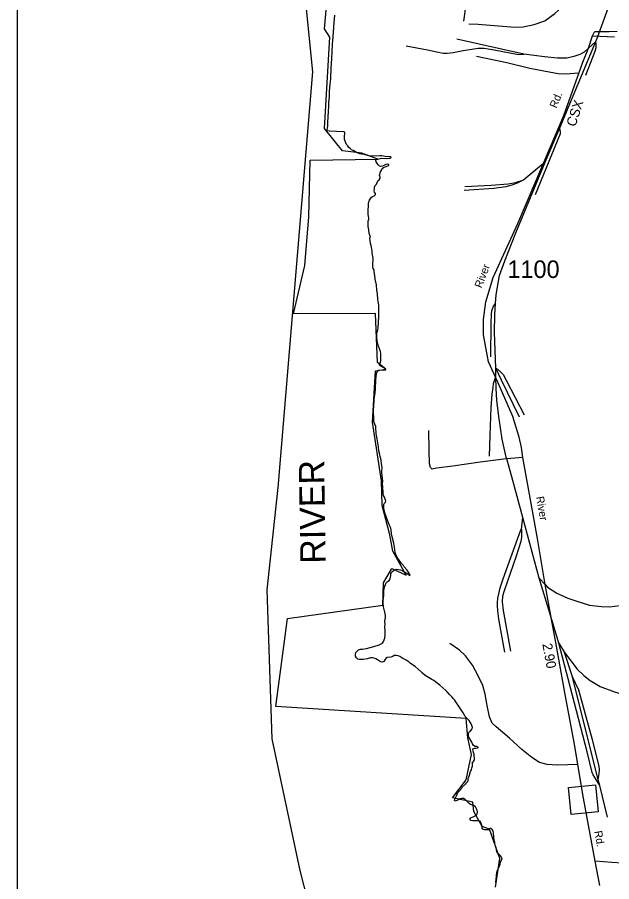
# Model space of a CAD drawing. Extents: x 1945482 to 2853149, y 66427 to 1015778.
# Drawn here: x 2313127 to 2318125, y 155248 to 162514 of the extents above; entities that cross this region are included whole.
import ezdxf

# ---------------------------------------------------------------- set-up
doc = ezdxf.new("R2010")
doc.units = 0
for name, color, linetype in [('Old_Level_11', 7, 'Continuous'), ('Old_Level_14', 7, 'Continuous'), ('Old_Level_17', 7, 'Continuous'), ('Old_Level_21', 7, 'Continuous'), ('Old_Level_28', 7, 'Continuous'), ('Old_Level_31', 7, 'Continuous'), ('Old_Level_32', 7, 'Continuous'), ('Old_Level_35', 7, 'Continuous'), ('Old_Level_44', 7, 'Continuous'), ('Old_Level_48', 7, 'Continuous'), ('Old_Level_49', 7, 'Continuous'), ('Old_Level_52', 7, 'Continuous'), ('Old_Level_60', 7, 'Continuous'), ('Old_Level_63', 7, 'Continuous'), ('Old_Level_8', 7, 'Continuous')]:
    doc.layers.add(name, color=color, linetype=linetype)

msp = doc.modelspace()

# ---------------------------------------------------------------- linework, layer by layer
at = {"layer": 'Old_Level_28'}
for points in [[(2318169.4, 162393.2), (2318104.3, 162392.5), (2317980, 162392.1)], [(2317962.5, 162357.8), (2318148.5, 162349.6)]]:
    msp.add_lwpolyline(points, dxfattribs=at)
at = {"layer": 'Old_Level_31'}
msp.add_lwpolyline([(2317761, 156040.2), (2317987.8, 156063.2), (2318010.8, 155836.2), (2317784, 155813.2)], close=True, dxfattribs=at)
at = {"layer": 'Old_Level_32'}
for points in [[(2317089.1, 159616.8), (2317047.7, 159844.4), (2317046.5, 159974.3), (2317066.6, 160121.2), (2317126.7, 160327.7), (2317334.1, 160779.3), (2317721.4, 161688), (2317881.2, 162136), (2317930.4, 162254.8), (2317962.5, 162357.8)], [(2317962.5, 162357.8), (2317980, 162392.1)], [(2317614.8, 157469.5), (2317563.8, 157746.7), (2317501.3, 158133.8), (2317422.1, 158566.8), (2317378.6, 158813.2), (2317367, 158896.8), (2317347.8, 158985.9), (2317292.7, 159157.7), (2317167.4, 159446.8), (2317089.1, 159616.8)], [(2318024.9, 155215.5), (2317984.7, 155420), (2317886.4, 155951.6), (2317838.6, 156234.4), (2317811.8, 156405.3), (2317733.4, 156820.3), (2317654, 157259.3), (2317614.8, 157469.5)]]:
    msp.add_lwpolyline(points, dxfattribs=at)
at = {"layer": 'Old_Level_35'}
msp.add_line((2317378.6, 158813.2), (2317241.7, 158803.7), dxfattribs=at)
for points in [[(2316881.4, 162480.4), (2316901.7, 162621.4), (2316932.2, 162912.7), (2316935, 162940)], [(2317840.8, 162044.5), (2317745.3, 162036.8), (2317675, 162039.9), (2317598.6, 162052.9), (2317435.4, 162082.3), (2317243.4, 162130.8), (2316986.9, 162184.6)], [(2317241.7, 158803.7), (2317236.8, 158803.3), (2317017.8, 158774.6), (2316789.1, 158739.7), (2316651.8, 158724.4), (2316616, 158716.7), (2316601.4, 158730.3), (2316592.4, 158759.8), (2316589.7, 158875.9), (2316587.2, 159039.9)], [(2317838.6, 156234.4), (2317756.7, 156231.2), (2317664.9, 156227.5), (2317582.7, 156232.2), (2317518, 156249.6), (2317454.3, 156293), (2317369.6, 156359.9), (2317265.7, 156454), (2317152, 156549.2), (2317120.6, 156580.1), (2317096.5, 156633), (2317076.6, 156730.4), (2317061.1, 156823.9), (2317042.1, 156897), (2317000.9, 156977.5), (2316953.3, 157067.8), (2316896.3, 157147.6), (2316846.2, 157195.5), (2316764, 157250.3)], [(2320019.6, 155318.3), (2319923.7, 155310.6), (2319746.3, 155297.4), (2319562.5, 155290.1), (2319444.2, 155293.6), (2319219.7, 155310.7), (2319006.7, 155328.2), (2318766, 155348.8), (2318536.9, 155373.6), (2318299.9, 155398.4), (2318125.2, 155409.5), (2317984.7, 155420)]]:
    msp.add_lwpolyline(points, dxfattribs=at)
at = {"layer": 'Old_Level_44'}
for p, q in [((2318008.4, 162353.8), (2318106.2, 162621.1)), ((2317384.6, 162204.3), (2316823.3, 162330.1)), ((2317992.5, 162310.4), (2318008.4, 162353.8)), ((2317689, 161584.3), (2317992.5, 162310.4)), ((2317992.5, 162310.4), (2317930.4, 162254.8)), ((2317566.5, 161297.2), (2317689, 161584.3)), ((2317502.8, 161244.5), (2317386.3, 161148.3)), ((2317566.5, 161297.2), (2317502.8, 161244.5)), ((2317151.2, 159500.3), (2317150.6, 159564.3)), ((2317149.7, 159495.2), (2317151.2, 159500.3)), ((2317151.4, 159490.5), (2317151.2, 159500.3)), ((2317366.2, 158212.4), (2317376.4, 158310.6)), ((2317514.5, 157800.2), (2317376.4, 158310.6)), ((2317514.5, 157800.2), (2317563.8, 157746.7)), ((2317614.8, 157469.5), (2317514.5, 157800.2)), ((2317680.1, 157254.4), (2317614.8, 157469.5)), ((2317680.1, 157254.4), (2317727.3, 157174.2)), ((2317795.4, 156968.8), (2317727.3, 157174.2)), ((2318011.7, 156105), (2317795.4, 156968.8)), ((2318025.8, 156057.7), (2318011.7, 156105)), ((2318090.2, 155790.1), (2318025.8, 156057.7))]:
    msp.add_line(p, q, dxfattribs=at)
for points in [[(2316924.2, 162460.1), (2317002.4, 162457.3), (2317309.3, 162431.4), (2317381.4, 162434.2), (2317472.6, 162452), (2317563.5, 162485.4), (2317645.1, 162544.8), (2317706.9, 162601.4), (2317752.9, 162651.1)], [(2316397.3, 162273.2), (2316574.8, 162240.5), (2316655.6, 162223.7), (2316707.8, 162213.6), (2316742, 162213), (2316791.6, 162218.9), (2316875, 162234.4), (2316948.8, 162245.2), (2317002.3, 162253.2), (2317052.5, 162253.2), (2317137, 162240.5), (2317340.4, 162200.6), (2317384.6, 162204.3)], [(2317930.4, 162254.8), (2317892, 162220.4), (2317856.6, 162201), (2317807.5, 162183), (2317747.9, 162170.8), (2317669.8, 162169.6), (2317559.4, 162181.4), (2317384.6, 162204.3)], [(2317907.5, 162027.1), (2317985.5, 162228.1), (2317994.5, 162258.6), (2317995.2, 162290.5), (2317992.5, 162310.4)], [(2317483.1, 161023.8), (2317692.9, 161536.5), (2317694.3, 161552.3), (2317689, 161584.3)], [(2317147.2, 160108.3), (2317154.5, 160180.8), (2317168.6, 160279.1), (2317179.9, 160343.6), (2317225.3, 160465.5), (2317317.7, 160701.2), (2317566.5, 161297.2)], [(2317386.3, 161148.3), (2317329.3, 161119.7), (2317284.1, 161102.2), (2317234.4, 161090.1), (2317134.9, 161074), (2316883.5, 161058.1)], [(2316888.4, 161090.5), (2317109.8, 161103.2), (2317253.5, 161112.8), (2317317, 161125.5), (2317386.3, 161148.3)], [(2317108.7, 159660.7), (2317109.7, 159942.7), (2317114.5, 160021), (2317115.8, 160047), (2317130, 160085.6), (2317147.2, 160108.3)], [(2317150.6, 159564.3), (2317138.6, 159868), (2317143.1, 160012.3), (2317147.2, 160108.3)], [(2317150.6, 159564.3), (2317165.1, 159555), (2317192, 159531.8), (2317212.7, 159512.6), (2317236.7, 159463.6), (2317388.3, 159171.6)], [(2317349.1, 159152), (2317198.6, 159464.1), (2317174.7, 159511.1), (2317150.6, 159564.3)], [(2317095.9, 158824), (2317103.1, 158998.2), (2317111.8, 159234.5), (2317119.2, 159347.1), (2317127.2, 159401.2), (2317131.8, 159435.5), (2317149.7, 159495.2)], [(2317376.4, 158310.6), (2317294, 158619.5), (2317241.7, 158803.7), (2317238.3, 158815.5), (2317202.4, 158968), (2317174.9, 159159.3), (2317157.4, 159294.4), (2317153.4, 159394.4), (2317151.4, 159490.5)], [(2317226.9, 157178.4), (2317186.6, 157393.1), (2317176.2, 157456.7), (2317167.3, 157524.2), (2317165.6, 157568.1), (2317164.6, 157592.1), (2317167, 157632.2), (2317175.7, 157668.6), (2317187.9, 157717), (2317209.1, 157786.1), (2317239.5, 157873.3), (2317288.4, 158005.2), (2317357, 158196), (2317366.2, 158212.4)], [(2317366.2, 158212.4), (2317366.9, 158144.2), (2317360.5, 158108.2), (2317321.1, 157984.5), (2317220.6, 157694.4), (2317206.4, 157647.9), (2317202.3, 157601.8), (2317211.1, 157527.9), (2317272.9, 157186.4)], [(2317563.8, 157746.7), (2317585.8, 157722.9), (2317663.5, 157673.8), (2317755.4, 157631.5), (2317824.3, 157608.3), (2317937.6, 157572.7), (2318038.2, 157560.6), (2318108.2, 157559.5), (2318191.8, 157568.7), (2318269, 157591.8), (2318347.5, 157632.9), (2318443.7, 157730.9), (2318592.9, 157898.6), (2318685.9, 157980.4), (2318761.6, 158039.5), (2318806.5, 158067.2)], [(2318025.8, 156057.7), (2317970, 156147.7), (2317961.5, 156165.1), (2317918.5, 156339.6), (2317776.6, 156888), (2317680.1, 157254.4)], [(2317727.3, 157174.2), (2317780.2, 157104.4), (2317834.9, 157034.4), (2317889.2, 156980.7), (2317944.6, 156939), (2318028.6, 156890.1), (2318146.7, 156842.9), (2318312.7, 156793.4), (2319291.1, 156585.9), (2319359.6, 156578.8), (2319427.6, 156577.2), (2319497, 156590.1), (2319581.8, 156621.3), (2319679.8, 156673.1), (2319730.4, 156713.2), (2319768.6, 156761), (2319822.5, 156857), (2319842.6, 156905.7)], [(2318011.7, 156105), (2318020, 156153.6), (2318022.6, 156187.5), (2318019.4, 156219.6), (2317964.4, 156439.6), (2317848.1, 156857), (2317795.4, 156968.8)]]:
    msp.add_lwpolyline(points, dxfattribs=at)
at = {"layer": 'Old_Level_48'}
for points in [[(2315710.4, 161579.5), (2315755.7, 162346.5), (2315710.4, 162417.2), (2315871.8, 164238.8)], [(2317147.8, 155201.2), (2317183.1, 155443.4), (2317097.3, 155690.6), (2317036.8, 155710.8), (2316966.2, 155837), (2316956.1, 155917.7), (2316784.6, 155953), (2316900.6, 156104.4), (2316946, 156316.4), (2316915.8, 156457.7), (2316900.6, 156619.1), (2315301.8, 156720.1), (2315397.7, 157461.8), (2316199.6, 157572.9), (2316204.6, 157759.6), (2316275.2, 157880.7), (2316396.3, 157825.2), (2316285.3, 158027), (2316260.1, 158163.3), (2316194.5, 158410.5), (2316189.5, 158617.4), (2316113.8, 159111.9), (2316139.1, 159540.9), (2316224.8, 159556), (2316154.2, 159611.5), (2316139.1, 160025.3), (2315447.9, 160020.1), (2315543.9, 160429), (2315579.2, 160837.7), (2315589.3, 161312.1), (2316159.2, 161322.2), (2316023.1, 161372.6), (2315861.7, 161392.8), (2315710.4, 161579.5)]]:
    msp.add_lwpolyline(points, dxfattribs=at)
at = {"layer": 'Old_Level_49'}
for points in [[(2315710.4, 161579.5), (2315755.7, 162346.5), (2315710.4, 162417.2), (2315871.8, 164238.8)], [(2317147.8, 155201.2), (2317183.1, 155443.4), (2317097.3, 155690.6), (2317036.8, 155710.8), (2316966.2, 155837), (2316956.1, 155917.7), (2316784.6, 155953), (2316900.6, 156104.4), (2316946, 156316.4), (2316915.8, 156457.7), (2316900.6, 156619.1), (2315301.8, 156720.1), (2315397.7, 157461.8), (2316199.6, 157572.9), (2316204.6, 157759.6), (2316275.2, 157880.7), (2316396.3, 157825.2), (2316285.3, 158027), (2316260.1, 158163.3), (2316194.5, 158410.5), (2316189.5, 158617.4), (2316113.8, 159111.9), (2316139.1, 159540.9), (2316224.8, 159556), (2316154.2, 159611.5), (2316139.1, 160025.3), (2315447.9, 160020.1), (2315543.9, 160429), (2315579.2, 160837.7), (2315589.3, 161312.1), (2316159.2, 161322.2), (2316023.1, 161372.6), (2315861.7, 161392.8), (2315710.4, 161579.5)]]:
    msp.add_lwpolyline(points, dxfattribs=at)
at = {"layer": 'Old_Level_52'}
msp.add_lwpolyline([(2315408.1, 164067), (2315607.7, 162054.2), (2315317.3, 158562.2), (2315224, 157700.8), (2315268.2, 156449.7), (2315501.7, 155343.5), (2315695.7, 154585.5), (2315964, 153221.3), (2316920.4, 148991.6), (2317162.1, 147612.8), (2317498.2, 146375.1), (2318329.6, 144823.8), (2319094.5, 143220.3), (2320166.2, 141551.5), (2320522.6, 140942.1), (2321397.1, 138973.7), (2322086, 137167.5), (2322248.1, 134963.6), (2322408.9, 131927.6), (2322579.8, 128889.8), (2322748.5, 125845.7), (2322867, 124333.8)], dxfattribs=at)
at = {"layer": 'Old_Level_60'}
for points in [[(2316141.5, 161313.7), (2316146.2, 161318.3), (2316188.5, 161329.6), (2316234.7, 161327.7), (2316250, 161328.5), (2316265, 161331), (2316269.5, 161334.9), (2316266.5, 161340.9), (2316220.5, 161344.7), (2316190.5, 161348.4), (2316175, 161348.9), (2316113.5, 161347), (2316098.2, 161347), (2316082.5, 161348.3), (2316052.5, 161358.2), (2316037.7, 161362.2), (2316021.7, 161363.6), (2316006.7, 161366.9), (2315978, 161376.6), (2315964, 161384.7), (2315951, 161393.5), (2315937.2, 161401), (2315925.2, 161410.1), (2315914.2, 161420.8), (2315907, 161434.3), (2315896, 161445.2), (2315890.2, 161459.9), (2315882.2, 161473.6), (2315878, 161488.5), (2315876.5, 161503.4), (2315881, 161549.2), (2315871, 161550.9), (2315810, 161553.3), (2315749.5, 161556.8), (2315734.7, 161559.8), (2315733.5, 161568.2), (2315734.5, 161583.5), (2315736.7, 161598.6), (2315739, 161629.5), (2315742.7, 161721.7), (2315746, 161768.2), (2315746.7, 161799), (2315750.5, 161844.7), (2315752.5, 161890.4), (2315758.7, 161951.1), (2315762, 161996.6), (2315763.2, 162027.9), (2315765.5, 162058.3), (2315766.5, 162089.3), (2315771.5, 162165.9), (2315776.7, 162288.2), (2315782.7, 162348.8), (2315790.5, 162470.9), (2315795.2, 162531.3)], [(2316138, 159384.3), (2316141.5, 159470.9), (2316144, 159486.3), (2316147.5, 159519.3), (2316153, 159534.7), (2316163, 159546.5), (2316178, 159551.1), (2316209.7, 159547.9), (2316225.7, 159550.4), (2316222.7, 159557.8), (2316183.5, 159581.6), (2316173.1, 159589.7), (2316172, 159598), (2316179.5, 159611.3), (2316183.7, 159626.1), (2316182.5, 159688.9), (2316180.5, 159704.9), (2316163, 159748.6), (2316153.5, 159795.4), (2316150, 159826.2), (2316149.5, 159842.4), (2316150.2, 159858.3), (2316158.5, 159888.2), (2316160.5, 159903.3), (2316165.7, 160000), (2316167, 160048.4), (2316166.5, 160095.4), (2316165, 160110.4), (2316161, 160125.5), (2316159.2, 160142.6), (2316158.7, 160158.1), (2316156.5, 160173.1), (2316155.5, 160188.9), (2316150.2, 160219.9), (2316145.7, 160265.9), (2316136.2, 160311.5), (2316132.5, 160343.9), (2316127.2, 160375.1), (2316126, 160390.5), (2316120, 160401.7), (2316115.5, 160416.1), (2316115.2, 160447.5), (2316120, 160472.9), (2316117.7, 160488.2), (2316116.7, 160503.6), (2316110.5, 160533.9), (2316109.7, 160550.2), (2316106.5, 160564.9), (2316104.7, 160580.7), (2316101.5, 160595.8), (2316097, 160611.4), (2316089.5, 160656.7), (2316095.5, 160667.1), (2316090, 160681.5), (2316086.5, 160696.1), (2316083, 160726.1), (2316078, 160756.7), (2316076.5, 160789.1), (2316077.2, 160804.8), (2316081.5, 160811.5), (2316082, 160826.2), (2316080.5, 160841.7), (2316076, 160856.8), (2316075.7, 160887.6), (2316079, 160934.3), (2316078.5, 160949.4), (2316081.5, 160963.2), (2316087.7, 160977.4), (2316104.5, 161000.8), (2316113.7, 161007.6), (2316128.2, 161012.1), (2316139, 161023.2), (2316139, 161032.9), (2316129.7, 161044.5), (2316127.7, 161056), (2316129.5, 161071.4), (2316130, 161086.5), (2316135.5, 161101.3), (2316145.7, 161111.4), (2316159, 161139.2), (2316168.5, 161148.2), (2316178.5, 161160.4), (2316176.5, 161171.3), (2316171.7, 161185.9), (2316181.2, 161214.8), (2316188, 161228.5), (2316193.5, 161242.8), (2316206, 161251.5), (2316219.5, 161258.3), (2316250, 161267), (2316250, 161277.4), (2316240.7, 161279.4), (2316225.5, 161275.3), (2316197.5, 161261.7), (2316181.7, 161258.4), (2316173, 161262.8), (2316162.2, 161273.5), (2316143.7, 161298.7), (2316141.5, 161313.7)], [(2316123.7, 157225), (2316168.7, 157240.3), (2316196.7, 157254.4), (2316205.7, 157267.6), (2316212.5, 157281.3), (2316216, 157296), (2316219.7, 157326.6), (2316219.5, 157359.3), (2316217.7, 157390), (2316219.2, 157406), (2316216.5, 157437.3), (2316222, 157468.1), (2316222, 157484.4), (2316217.2, 157514.4), (2316207, 157559.7), (2316202.5, 157591.5), (2316202.2, 157608.1), (2316207.5, 157654.8), (2316207.2, 157685.7), (2316209.5, 157701.1), (2316215.7, 157731.6), (2316221.5, 157745.6), (2316229.5, 157759.2), (2316240, 157770.4), (2316252.2, 157779.4), (2316261, 157792.5), (2316265.5, 157806.9), (2316266.2, 157822.5), (2316268.7, 157837.4), (2316277, 157850.8), (2316287.5, 157861.7), (2316300.7, 157869.9), (2316316, 157874.3), (2316331.5, 157873.3), (2316347.5, 157869.3), (2316363, 157864.2), (2316431.2, 157821.9), (2316427.5, 157830.6), (2316411.5, 157857.7), (2316402.2, 157870.9), (2316380.5, 157893.6), (2316372.7, 157906.7), (2316361.2, 157918.9), (2316351.7, 157931.2), (2316324.7, 157970.7), (2316308.7, 157999.1), (2316303.2, 158014.7), (2316298.7, 158061), (2316292, 158093.9), (2316276.2, 158158.1), (2316273, 158174.7), (2316270.2, 158204.8), (2316266.7, 158220.7), (2316260, 158236.2), (2316252.5, 158250.2), (2316248, 158264.7), (2316230.5, 158308.5), (2316220, 158339.2), (2316211.7, 158370.6), (2316208.7, 158386), (2316207.5, 158401.9), (2316207.5, 158417.9), (2316211.2, 158428.1), (2316223, 158437.9), (2316224.5, 158450.1), (2316219, 158464.1), (2316214.2, 158479.2), (2316206.5, 158493.3), (2316203.2, 158508.3), (2316200.5, 158573), (2316198.7, 158588.1), (2316199.5, 158619.6), (2316198.2, 158635.5), (2316193.5, 158666.3), (2316192.5, 158681.6), (2316192, 158697.2), (2316193.7, 158729.1), (2316192.7, 158744.7), (2316183, 158806.4), (2316179, 158823.1), (2316174.5, 158837.7), (2316167, 158871), (2316163.5, 158902.3), (2316157.2, 158936.3), (2316152.5, 158969.6), (2316146.5, 158999.8), (2316144.2, 159015.9), (2316141.7, 159065.7), (2316140.2, 159080.9), (2316139, 159081.2), (2316136.5, 159086.7), (2316125, 159115.2), (2316123.5, 159124.9), (2316124, 159126.8), (2316122.7, 159208.8), (2316128, 159288.2), (2316127.7, 159304.5), (2316129.7, 159321.2), (2316132.7, 159336.7), (2316138, 159384.3)], [(2316863.5, 156033.6), (2316871, 156046.9), (2316894, 156066.8), (2316903, 156078.9), (2316914.2, 156089.5), (2316917, 156098), (2316917.2, 156114.2), (2316922, 156128.6), (2316928.2, 156143.7), (2316938.2, 156174.5), (2316944.5, 156189.6), (2316949.5, 156204.4), (2316953.2, 156220.1), (2316954, 156251.9), (2316962.5, 156259), (2316971.2, 156271.9), (2316969.2, 156319.7), (2316963.5, 156334.3), (2316959.5, 156349.1), (2316957.5, 156365.5), (2316970, 156370.8), (2316986.2, 156370.8), (2317001.5, 156373.6), (2317002, 156380.1), (2316991.2, 156384.3), (2316975.5, 156385.4), (2316961.5, 156392.8), (2316953.5, 156406.4), (2316948.2, 156421.6), (2316940.5, 156435.5), (2316930.7, 156448.1), (2316924, 156462.6), (2316920, 156478.7), (2316921, 156495), (2316928, 156509.4), (2316939.5, 156519.8), (2316950.5, 156531.9), (2316953, 156545), (2316948.5, 156560.4), (2316942.5, 156575.6), (2316926.7, 156604.2), (2316915.7, 156614.8), (2316903, 156624.9), (2316893, 156638), (2316876.5, 156666.4), (2316815, 156761), (2316804.5, 156774), (2316793.2, 156786.2), (2316783.2, 156799.1), (2316772.5, 156810.3), (2316761, 156820.4), (2316740, 156843.9), (2316728.7, 156855.1), (2316704, 156877.2), (2316680.5, 156900.1), (2316642.2, 156929), (2316628.2, 156938.5), (2316613.5, 156946.9), (2316557.5, 156982.2), (2316533.5, 157002.3), (2316521.2, 157011.5), (2316472.5, 157055.7), (2316433.2, 157081.7), (2316422, 157092.5), (2316397.5, 157110.9), (2316369.5, 157125.5), (2316342, 157141.6), (2316328, 157147.6), (2316311.7, 157150.7), (2316296, 157149), (2316283, 157140.6), (2316268.2, 157135.6), (2316236.2, 157132.6), (2316224.5, 157125.4), (2316216.5, 157112.2), (2316207.5, 157099.6), (2316196.2, 157093.2), (2316181.5, 157097.3), (2316156, 157114.2), (2316142.2, 157121.4), (2316127.7, 157126.9), (2316113, 157129.9), (2316097.5, 157128.6), (2316067.5, 157121.6), (2316035.7, 157116.1), (2316020, 157114.9), (2316004, 157114.8), (2315989.5, 157119.1), (2315978.2, 157130.5), (2315971, 157143.7), (2315970, 157158.9), (2315974.5, 157173.9), (2315984.2, 157185.5), (2315994.7, 157196.3), (2316002.7, 157199.6), (2316013.5, 157201.8), (2316030, 157203.7), (2316062, 157209), (2316093, 157217.6), (2316123.7, 157225)], [(2317151.7, 155242.1), (2317153, 155274.1), (2317155.7, 155289.4), (2317156.7, 155305.4), (2317161.7, 155337.5), (2317167, 155351.9), (2317182.2, 155379.6), (2317186.7, 155395.3), (2317189, 155411), (2317196.5, 155425.1), (2317202.5, 155439.2), (2317199.2, 155455), (2317189, 155466.8), (2317177.5, 155477), (2317167, 155487.8), (2317158.5, 155501.6), (2317152.5, 155533.5), (2317143, 155564.5), (2317141, 155580.1), (2317136.5, 155594.8), (2317132.7, 155626), (2317130.5, 155656.9), (2317126.7, 155672.7), (2317120.2, 155686.6), (2317108.2, 155697.8), (2317099, 155696.2), (2317088, 155685.2), (2317072.5, 155684), (2317056.5, 155685.5), (2317040.5, 155689.9), (2317034.7, 155699.2), (2317034.5, 155715.1), (2317030, 155729.7), (2317024.5, 155744.4), (2317017.5, 155757.8), (2317003, 155760.2), (2316987.5, 155761), (2316955, 155760.5), (2316939.2, 155762.7), (2316933.7, 155769.4), (2316935.5, 155783), (2316945.5, 155787.8), (2316960.2, 155792), (2316987.5, 155807.7), (2316993.2, 155817.2), (2316995, 155833.4), (2316993, 155848.4), (2316979.5, 155876.5), (2316968.5, 155885.7), (2316938.5, 155897.2), (2316924.7, 155906), (2316914, 155916.9), (2316904.2, 155929.2), (2316893.2, 155940.4), (2316879.5, 155947.1), (2316864, 155948.8), (2316849.5, 155944.5), (2316836.5, 155936.8), (2316821.7, 155930.8), (2316806, 155926.2), (2316801.5, 155930.7), (2316804.7, 155941.5), (2316819, 155969.7), (2316824.2, 155984.3), (2316831.5, 155998.5), (2316842.5, 156008.7), (2316863.5, 156033.6)]]:
    msp.add_lwpolyline(points, dxfattribs=at)
at = {"layer": 'Old_Level_63'}
msp.add_lwpolyline([(2313126.6, 192135.8), (2313126.6, 148693.6), (2316886.9, 148684.9)], dxfattribs=at)

# ---------------------------------------------------------------- texts
at = {"layer": 'Old_Level_11'}
for s, rotation, p in [('Rd.', 67.47205, (2317659.9, 161744.9)), ('River', 68.94678, (2317029.7, 160232.7)), ('River', 279.44354, (2317489, 158482.2)), ('Rd.', 280.15666, (2317977.6, 155670.9))]:
    msp.add_text(s, height=65.62, rotation=rotation, dxfattribs=at).set_placement(p)
at = {"layer": 'Old_Level_14'}
msp.add_text('CSX', height=82.02, rotation=72.18788, dxfattribs=at).set_placement((2317819, 161588.6))
at = {"layer": 'Old_Level_17'}
msp.add_text('2.90', height=82.02, rotation=280.55227, dxfattribs=at).set_placement((2317540.9, 157244.5))
at = {"layer": 'Old_Level_21'}
msp.add_text('RIVER', height=213.25, rotation=90.90101, dxfattribs=at).set_placement((2315720.5, 157922.6))
at = {"layer": 'Old_Level_8'}
msp.add_text('1100', height=147.64, dxfattribs=at).set_placement((2317247.4, 160322.5))

doc.saveas('drawing.dxf')
